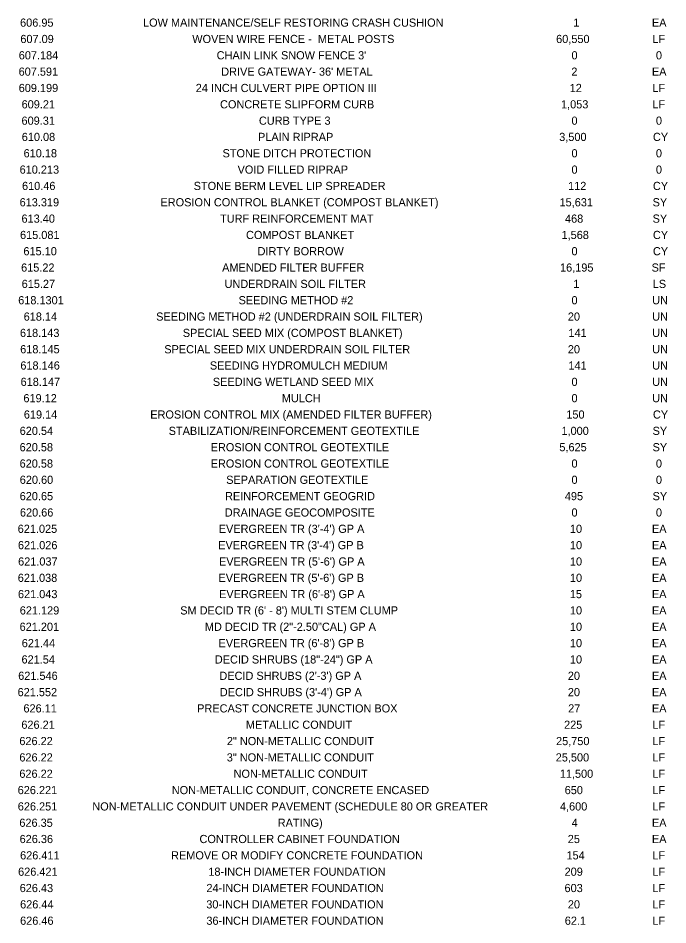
# Model space of a CAD drawing. Extents: x -18.7 to 5.6, y -2.7 to 4.
# Drawn here: x 0.03 to 0.812, y -1.562 to -0.468 of the extents above; entities that cross this region are included whole.
import ezdxf

# ---------------------------------------------------------------- set-up
doc = ezdxf.new("R2010")
doc.units = 0
doc.layers.add('ANNOTATION', color=7, linetype='Continuous')

msp = doc.modelspace()

# ---------------------------------------------------------------- texts
at = {"layer": 'ANNOTATION'}
for s, height, p in [('606.95', 0.00984, (0.0319, -0.4787)), ('LOW MAINTENANCE/SELF RESTORING CRASH CUSHION', 0.009843, (0.18, -0.4787)), ('1', 0.00984, (0.6984, -0.4787)), ('EA', 0.00984, (0.7931, -0.4787)), ('607.09', 0.00984, (0.0322, -0.4984)), ('WOVEN WIRE FENCE -  METAL POSTS', 0.009843, (0.2393, -0.4984)), ('60,550', 0.00984, (0.6777, -0.4984)), ('LF', 0.00984, (0.7937, -0.4984)), ('607.184', 0.00984, (0.0303, -0.5181)), ("CHAIN LINK SNOW FENCE 3'", 0.009843, (0.2687, -0.5181)), ('0', 0.00984, (0.6962, -0.5181)), ('0', 0.00984, (0.7979, -0.5181)), ('607.591', 0.00984, (0.0301, -0.5378)), ("DRIVE GATEWAY- 36' METAL", 0.009843, (0.2742, -0.5378)), ('2', 0.00984, (0.696, -0.5378)), ('EA', 0.00984, (0.7931, -0.5378)), ('609.199', 0.00984, (0.0302, -0.5575)), ('24 INCH CULVERT PIPE OPTION III', 0.009843, (0.2435, -0.5575)), ('12', 0.00984, (0.694, -0.5575)), ('LF', 0.00984, (0.7937, -0.5575)), ('609.21', 0.00984, (0.0337, -0.5772)), ('CONCRETE SLIPFORM CURB', 0.009843, (0.2728, -0.5772)), ('1,053', 0.00984, (0.6836, -0.5772)), ('LF', 0.00984, (0.7937, -0.5772)), ('609.31', 0.00984, (0.0336, -0.5969)), ('CURB TYPE 3', 0.009843, (0.3196, -0.5969)), ('0', 0.00984, (0.6962, -0.5969)), ('0', 0.00984, (0.7979, -0.5969)), ('610.08', 0.00984, (0.0339, -0.6165)), ('PLAIN RIPRAP', 0.009843, (0.3185, -0.6165)), ('3,500', 0.00984, (0.6814, -0.6165)), ('CY', 0.00984, (0.7943, -0.6165)), ('610.18', 0.00984, (0.0361, -0.6362)), ('STONE DITCH PROTECTION', 0.009843, (0.2758, -0.6362)), ('0', 0.00984, (0.6962, -0.6362)), ('0', 0.00984, (0.7979, -0.6362)), ('610.213', 0.00984, (0.0313, -0.6559)), ('VOID FILLED RIPRAP', 0.009843, (0.2939, -0.6559)), ('0', 0.00984, (0.6962, -0.6559)), ('0', 0.00984, (0.7979, -0.6559)), ('610.46', 0.00984, (0.0342, -0.6756)), ('STONE BERM LEVEL LIP SPREADER ', 0.009843, (0.241, -0.6756)), ('112', 0.00984, (0.6921, -0.6756)), ('CY', 0.00984, (0.7943, -0.6756)), ('613.319', 0.00984, (0.0313, -0.6953)), ('EROSION CONTROL BLANKET (COMPOST BLANKET)', 0.009843, (0.201, -0.6953)), ('15,631', 0.00984, (0.6818, -0.6953)), ('SY', 0.00984, (0.7939, -0.6953)), ('613.40', 0.00984, (0.0336, -0.715)), ('TURF REINFORCEMENT MAT', 0.009843, (0.2728, -0.715)), ('468', 0.00984, (0.6884, -0.715)), ('SY', 0.00984, (0.7939, -0.715)), ('615.081', 0.00984, (0.0318, -0.7347)), ('COMPOST BLANKET', 0.009843, (0.3041, -0.7347)), ('1,568', 0.00984, (0.6842, -0.7347)), ('CY', 0.00984, (0.7943, -0.7347)), ('615.10', 0.00984, (0.0359, -0.7543)), ('DIRTY BORROW', 0.009843, (0.318, -0.7543)), ('0', 0.00984, (0.6962, -0.7543)), ('CY', 0.00984, (0.7943, -0.7543)), ('615.22', 0.00984, (0.0331, -0.774)), ('AMENDED FILTER BUFFER', 0.009843, (0.2753, -0.774)), ('16,195', 0.00984, (0.6824, -0.774)), ('SF', 0.00984, (0.7927, -0.774)), ('615.27', 0.00984, (0.0338, -0.7937)), ('UNDERDRAIN SOIL FILTER', 0.009843, (0.2782, -0.7937)), ('1', 0.00984, (0.6984, -0.7937)), ('LS', 0.00984, (0.7941, -0.7937)), ('618.1301', 0.00984, (0.0296, -0.8134)), ('SEEDING METHOD #2', 0.009843, (0.2951, -0.8134)), ('0', 0.00984, (0.6962, -0.8134)), ('UN', 0.00984, (0.7934, -0.8134)), ('618.14', 0.00984, (0.0362, -0.8331)), ('SEEDING METHOD #2 (UNDERDRAIN SOIL FILTER)', 0.009843, (0.1958, -0.8331)), ('20', 0.00984, (0.6918, -0.8331)), ('UN', 0.00984, (0.7934, -0.8331)), ('618.143', 0.00984, (0.0317, -0.8528)), ('SPECIAL SEED MIX (COMPOST BLANKET)', 0.009843, (0.2279, -0.8528)), ('141', 0.00984, (0.6925, -0.8528)), ('UN', 0.00984, (0.7934, -0.8528)), ('618.145', 0.00984, (0.032, -0.8725)), ('SPECIAL SEED MIX UNDERDRAIN SOIL FILTER', 0.009843, (0.2056, -0.8725)), ('20', 0.00984, (0.6918, -0.8725)), ('UN', 0.00984, (0.7934, -0.8725)), ('618.146', 0.00984, (0.0322, -0.8921)), ('SEEDING HYDROMULCH MEDIUM', 0.009843, (0.2605, -0.8921)), ('141', 0.00984, (0.6925, -0.8921)), ('UN', 0.00984, (0.7934, -0.8921)), ('618.147', 0.00984, (0.0325, -0.9118)), ('SEEDING WETLAND SEED MIX', 0.009843, (0.2641, -0.9118)), ('0', 0.00984, (0.6962, -0.9118)), ('UN', 0.00984, (0.7934, -0.9118)), ('619.12', 0.00984, (0.0359, -0.9315)), ('MULCH', 0.00984, (0.3472, -0.9315)), ('0', 0.00984, (0.6962, -0.9315)), ('UN', 0.00984, (0.7934, -0.9315)), ('619.14', 0.00984, (0.0364, -0.9512)), ('EROSION CONTROL MIX (AMENDED FILTER BUFFER)', 0.009843, (0.1887, -0.9512)), ('150', 0.00984, (0.69, -0.9512)), ('CY', 0.00984, (0.7943, -0.9512)), ('620.54', 0.00984, (0.0314, -0.9709)), ('STABILIZATION/REINFORCEMENT GEOTEXTILE', 0.009843, (0.2109, -0.9709)), ('1,000', 0.00984, (0.6841, -0.9709)), ('SY', 0.00984, (0.7939, -0.9709)), ('620.58', 0.00984, (0.0313, -0.9906)), ('EROSION CONTROL GEOTEXTILE', 0.009843, (0.2615, -0.9906)), ('5,625', 0.00984, (0.6816, -0.9906)), ('SY', 0.00984, (0.7939, -0.9906)), ('620.58', 0.00984, (0.0313, -1.0103)), ('EROSION CONTROL GEOTEXTILE', 0.009843, (0.2615, -1.0103)), ('0', 0.00984, (0.6962, -1.0103)), ('0', 0.00984, (0.7979, -1.0103)), ('620.60', 0.00984, (0.0315, -1.0299)), ('SEPARATION GEOTEXTILE', 0.009843, (0.2802, -1.0299)), ('0', 0.00984, (0.6962, -1.0299)), ('0', 0.00984, (0.7979, -1.0299)), ('620.65', 0.00984, (0.0314, -1.0496)), ('REINFORCEMENT GEOGRID', 0.009843, (0.2788, -1.0496)), ('495', 0.00984, (0.6882, -1.0496)), ('SY', 0.00984, (0.7939, -1.0496)), ('620.66', 0.00984, (0.0317, -1.0693)), ('DRAINAGE GEOCOMPOSITE', 0.009843, (0.2785, -1.0693)), ('0', 0.00984, (0.6962, -1.0693)), ('0', 0.00984, (0.7979, -1.0693)), ('621.025', 0.00984, (0.029, -1.089)), ("EVERGREEN TR (3'-4') GP A", 0.009843, (0.2712, -1.089)), ('10', 0.00984, (0.6943, -1.089)), ('EA', 0.00984, (0.7931, -1.089)), ('621.026', 0.00984, (0.0293, -1.1087)), ("EVERGREEN TR (3'-4') GP B", 0.009843, (0.2706, -1.1087)), ('10', 0.00984, (0.6943, -1.1087)), ('EA', 0.00984, (0.7931, -1.1087)), ('621.037', 0.00984, (0.0295, -1.1284)), ("EVERGREEN TR (5'-6') GP A", 0.009843, (0.2715, -1.1284)), ('10', 0.00984, (0.6943, -1.1284)), ('EA', 0.00984, (0.7931, -1.1284)), ('621.038', 0.00984, (0.0291, -1.1481)), ("EVERGREEN TR (5'-6') GP B", 0.009843, (0.2709, -1.1481)), ('10', 0.00984, (0.6943, -1.1481)), ('EA', 0.00984, (0.7931, -1.1481)), ('621.043', 0.00984, (0.0293, -1.1677)), ("EVERGREEN TR (6'-8') GP A", 0.009843, (0.2716, -1.1677)), ('15', 0.00984, (0.6942, -1.1677)), ('EA', 0.00984, (0.7931, -1.1677)), ('621.129', 0.00984, (0.0315, -1.1874)), ("SM DECID TR (6' - 8') MULTI STEM CLUMP", 0.009843, (0.2248, -1.1874)), ('10', 0.00984, (0.6943, -1.1874)), ('EA', 0.00984, (0.7931, -1.1874)), ('621.201', 0.00984, (0.0313, -1.2071)), ('MD DECID TR (2"-2.50"CAL) GP A', 0.009843, (0.2545, -1.2071)), ('10', 0.00984, (0.6943, -1.2071)), ('EA', 0.00984, (0.7931, -1.2071)), ('621.44', 0.00984, (0.0339, -1.2268)), ("EVERGREEN TR (6'-8') GP B", 0.009843, (0.271, -1.2268)), ('10', 0.00984, (0.6943, -1.2268)), ('EA', 0.00984, (0.7931, -1.2268)), ('621.54', 0.00984, (0.0336, -1.2465)), ('DECID SHRUBS (18"-24") GP A', 0.009843, (0.2665, -1.2465)), ('10', 0.00984, (0.6943, -1.2465)), ('EA', 0.00984, (0.7931, -1.2465)), ('621.546', 0.00984, (0.0296, -1.2662)), ("DECID SHRUBS (2'-3') GP A", 0.009843, (0.272, -1.2662)), ('20', 0.00984, (0.6918, -1.2662)), ('EA', 0.00984, (0.7931, -1.2662)), ('621.552', 0.00984, (0.0289, -1.2859)), ("DECID SHRUBS (3'-4') GP A", 0.009843, (0.2725, -1.2859)), ('20', 0.00984, (0.6918, -1.2859)), ('EA', 0.00984, (0.7931, -1.2859)), ('626.11', 0.00984, (0.0359, -1.3055)), ('PRECAST CONCRETE JUNCTION BOX', 0.009843, (0.2452, -1.3055)), ('27', 0.00984, (0.6922, -1.3055)), ('EA', 0.00984, (0.7931, -1.3055)), ('626.21', 0.00984, (0.0334, -1.3252)), ('METALLIC CONDUIT', 0.009843, (0.3039, -1.3252)), ('225', 0.00984, (0.6873, -1.3252)), ('LF', 0.00984, (0.7937, -1.3252)), ('626.22', 0.00984, (0.031, -1.3449)), ('2" NON-METALLIC CONDUIT', 0.009843, (0.281, -1.3449)), ('25,750', 0.00984, (0.6776, -1.3449)), ('LF', 0.00984, (0.7937, -1.3449)), ('626.22', 0.00984, (0.031, -1.3646)), ('3" NON-METALLIC CONDUIT', 0.009843, (0.2809, -1.3646)), ('25,500', 0.00984, (0.6772, -1.3646)), ('LF', 0.00984, (0.7937, -1.3646)), ('626.22', 0.00984, (0.031, -1.3843)), ('NON-METALLIC CONDUIT', 0.009843, (0.2891, -1.3843)), ('11,500', 0.00984, (0.6821, -1.3843)), ('LF', 0.00984, (0.7937, -1.3843)), ('626.221', 0.00984, (0.029, -1.404)), ('NON-METALLIC CONDUIT, CONCRETE ENCASED', 0.009843, (0.2146, -1.404)), ('650', 0.00984, (0.688, -1.404)), ('LF', 0.00984, (0.7937, -1.404)), ('626.251', 0.00984, (0.0291, -1.4237)), ('NON-METALLIC CONDUIT UNDER PAVEMENT (SCHEDULE 80 OR GREATER ', 0.009843, (0.1189, -1.4237)), ('4,600', 0.00984, (0.6823, -1.4237)), ('LF', 0.00984, (0.7937, -1.4237)), ('626.35', 0.00984, (0.031, -1.4434)), ('RATING)', 0.00984, (0.3423, -1.4434)), ('4', 0.00984, (0.6964, -1.4434)), ('EA', 0.00984, (0.7931, -1.4434)), ('626.36', 0.00984, (0.0313, -1.463)), ('CONTROLLER CABINET FOUNDATION', 0.009843, (0.248, -1.463)), ('25', 0.00984, (0.6917, -1.463)), ('EA', 0.00984, (0.7931, -1.463)), ('626.411', 0.00984, (0.0319, -1.4827)), ('REMOVE OR MODIFY CONCRETE FOUNDATION', 0.009843, (0.2138, -1.4827)), ('154', 0.00984, (0.6902, -1.4827)), ('LF', 0.00984, (0.7937, -1.4827)), ('626.421', 0.00984, (0.0295, -1.5024)), ('18-INCH DIAMETER FOUNDATION', 0.009843, (0.2587, -1.5024)), ('209', 0.00984, (0.6879, -1.5024)), ('LF', 0.00984, (0.7937, -1.5024)), ('626.43', 0.00984, (0.0314, -1.5221)), ('24-INCH DIAMETER FOUNDATION', 0.009843, (0.2564, -1.5221)), ('603', 0.00984, (0.6878, -1.5221)), ('LF', 0.00984, (0.7937, -1.5221)), ('626.44', 0.00984, (0.0319, -1.5418)), ('30-INCH DIAMETER FOUNDATION', 0.009843, (0.2562, -1.5418)), ('20', 0.00984, (0.6918, -1.5418)), ('LF', 0.00984, (0.7937, -1.5418)), ('626.46', 0.00984, (0.0319, -1.5615)), ('36-INCH DIAMETER FOUNDATION', 0.009843, (0.2563, -1.5615)), ('62.1', 0.00984, (0.6881, -1.5615)), ('LF', 0.00984, (0.7937, -1.5615))]:
    msp.add_text(s, height=height, dxfattribs=at).set_placement(p)

doc.saveas('drawing.dxf')
